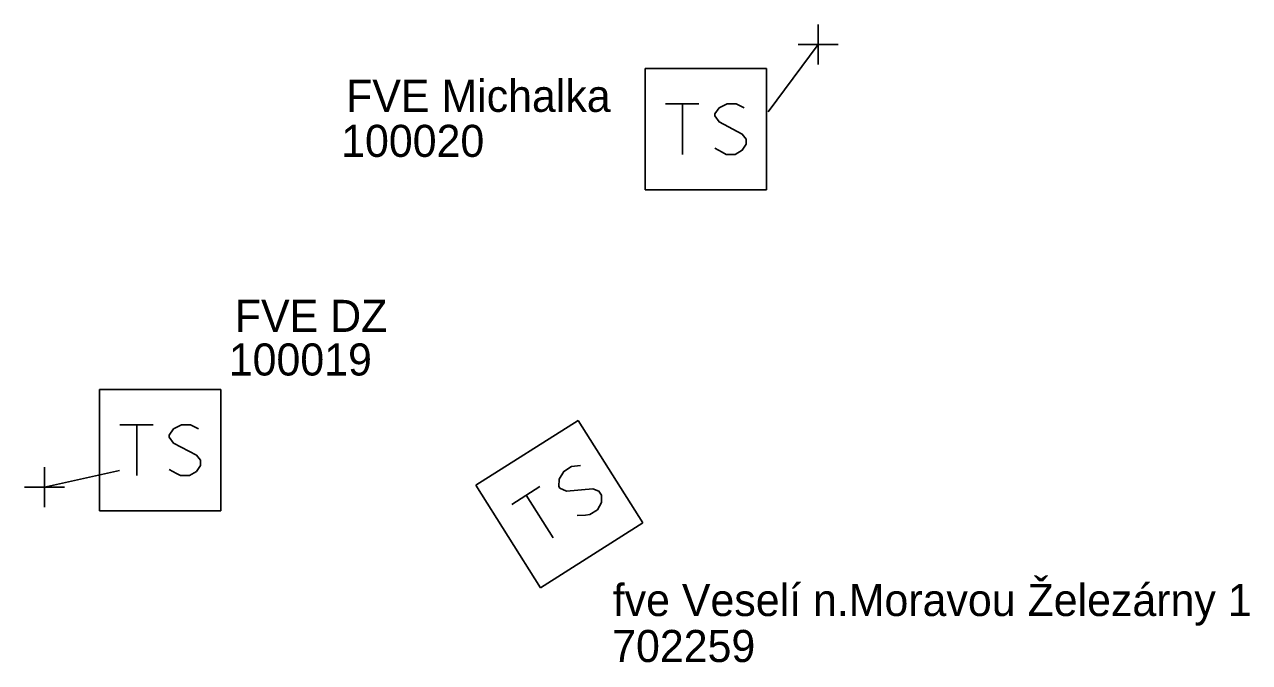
# Model space of a CAD drawing. Extents: x -545577 to -544860, y -1195056 to -1194677.
# Drawn here: x -544897.96 to -544859.76, y -1194696.65 to -1194676.76 of the extents above; entities that cross this region are included whole.
import ezdxf

# ---------------------------------------------------------------- set-up
doc = ezdxf.new("R2010")
doc.units = 0
for name, color, linetype in [('Vrstva 1', 7, 'Continuous'), ('Vrstva 25', 7, 'Continuous'), ('Vrstva 26', 7, 'Continuous'), ('Vrstva 27', 7, 'Continuous'), ('Vrstva 34', 7, 'Continuous'), ('Vrstva 59', 7, 'Continuous'), ('Vrstva 6', 7, 'Continuous')]:
    doc.layers.add(name, color=color, linetype=linetype)

# ---------------------------------------------------------------- blocks, each defined once
blk = doc.blocks.new('NN800')
at = {"layer": 'Vrstva 1'}
for points in [[(-0.442, 0.442), (0.442, -0.442)], [(-0.442, -0.442), (0.442, 0.442)]]:
    blk.add_lwpolyline(points, dxfattribs=at)
blk = doc.blocks.new('NN640')
at = {"layer": 'Vrstva 6'}
for points in [[(-1.89, 1.889), (1.889, 1.889)], [(-1.89, -1.89), (-1.89, 1.889)], [(1.889, 1.889), (1.889, -1.89)], [(-1.26, 0.787), (-0.221, 0.787)], [(-0.725, 0.787), (-0.725, -0.788)], [(1.197, 0.661), (0.945, 0.787), (0.661, 0.787), (0.409, 0.661), (0.283, 0.472), (0.283, 0.409), (0.409, 0.22), (1.133, -0.158), (1.259, -0.316), (1.259, -0.473), (1.133, -0.662), (0.913, -0.788), (0.629, -0.788), (0.503, -0.725), (0.283, -0.599)], [(1.889, -1.89), (-1.89, -1.89)]]:
    blk.add_lwpolyline(points, dxfattribs=at)

msp = doc.modelspace()

# ---------------------------------------------------------------- linework, layer by layer
at = {"layer": 'Vrstva 59'}
for points in [[(-544874.772, -1194679.481), (-544873.216, -1194677.389)], [(-544894.995, -1194690.664), (-544897.334, -1194691.184)]]:
    msp.add_lwpolyline(points, dxfattribs=at)

# ---------------------------------------------------------------- block references
at = {"layer": 'Vrstva 25'}
for p in [(-544876.713, -1194680.022), (-544893.727, -1194690.03)]:
    msp.add_blockref('NN640', p, dxfattribs=at)
at = {"layer": 'Vrstva 25', "rotation": 32.363291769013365}
msp.add_blockref('NN640', (-544881.284, -1194691.709), dxfattribs=at)
at = {"layer": 'Vrstva 34'}
for p, rotation in [((-544873.216, -1194677.389), 45.00000009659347), ((-544897.334, -1194691.184), 44.99999995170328)]:
    msp.add_blockref('NN800', p, dxfattribs=dict(at, rotation=rotation))

# ---------------------------------------------------------------- texts
at = {"layer": 'Vrstva 26'}
for s, p in [('100020', (-544888.086, -1194680.89)), ('100019', (-544891.59, -1194687.703)), ('702259', (-544879.636, -1194696.632))]:
    msp.add_text(s, height=1, dxfattribs=at).set_placement(p)
at = {"layer": 'Vrstva 27'}
for s, p in [('FVE Michalka', (-544887.932, -1194679.487)), ('FVE DZ', (-544891.401, -1194686.344)), ('fve Veselí n.Moravou Železárny 1', (-544879.618, -1194695.198))]:
    msp.add_text(s, height=1, dxfattribs=at).set_placement(p)

doc.saveas('drawing.dxf')
